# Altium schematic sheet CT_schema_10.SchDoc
size 278 x 170 mm
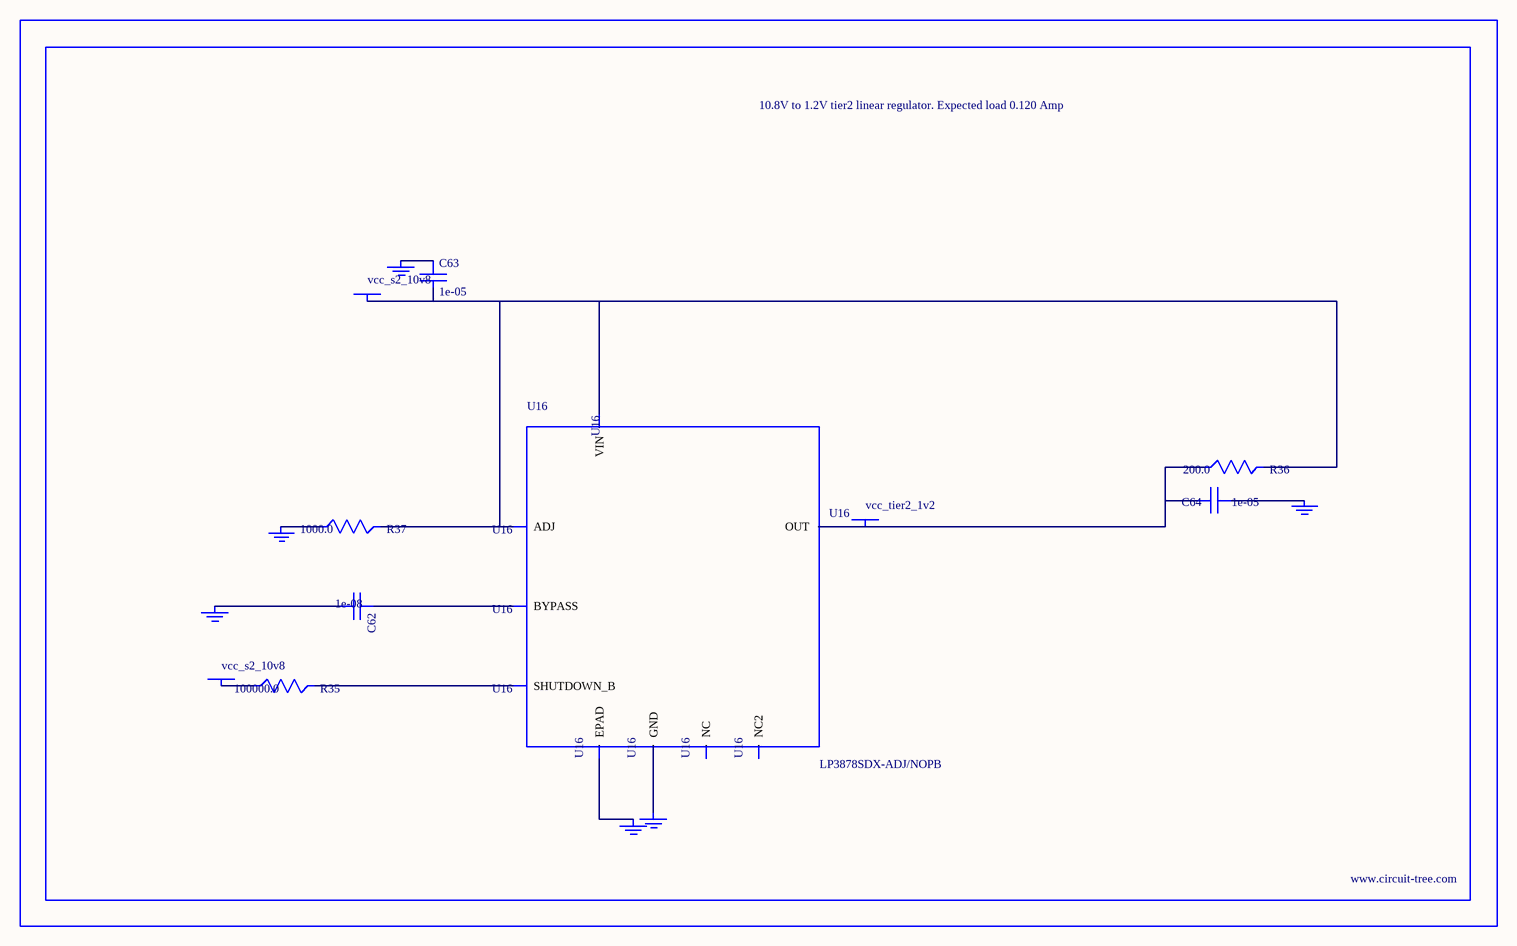
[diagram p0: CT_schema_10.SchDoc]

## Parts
BORDER9  (no value)
C62  1e-08  [C0402]
C63  1e-05  [C1206]
C64  1e-05  [C0805]
GND_INSTANCE_9_0  (no value)
GND_INSTANCE_9_1  (no value)
GND_INSTANCE_9_2  (no value)
GND_INSTANCE_9_3  (no value)
GND_INSTANCE_9_4  (no value)
GND_INSTANCE_9_5  (no value)
POWER_INSTANCE_9_0  vcc_s2_10v8
POWER_INSTANCE_9_1  vcc_s2_10v8
POWER_INSTANCE_9_2  vcc_tier2_1v2
R35  100000.0  [R0603]
R36  200.0  [R0603]
R37  1000.0  [R0603]
U16  LP3878SDX-ADJ/NOPB  [WSON-8]

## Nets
NetC62_1: C62.1 U16.1(BYPASS)
NetC62_2: C62.2 GND_INSTANCE_9_0.0(GND)
NetC63_1: C63.1 GND_INSTANCE_9_1.0(GND)
NetC63_2: C63.2 POWER_INSTANCE_9_0.0(PWR) R36.2 R37.2 U16.4(VIN) U16.6(ADJ)
NetC64_1: C64.1 GND_INSTANCE_9_2.0(GND)
NetC64_2: C64.2 POWER_INSTANCE_9_2.0(PWR) R36.1 U16.5(OUT)
NetGND_INSTANCE_9_3_0: GND_INSTANCE_9_3.0(GND) R37.1
NetGND_INSTANCE_9_4_0: GND_INSTANCE_9_4.0(GND) U16.PAD(EPAD)
NetGND_INSTANCE_9_5_0: GND_INSTANCE_9_5.0(GND) U16.3(GND)
NetPOWER_INSTANCE_9_1_0: POWER_INSTANCE_9_1.0(PWR) R35.1
NetR35_2: R35.2 U16.8(SHUTDOWN_B)

Not connected (* = marked no-connect by the designer): U16 2(NC) 7(NC2)

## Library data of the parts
BORDER9 = BORDER_PAGE9
C62 = C0402C103K3RAC
C63 = C1206C106K3RACTU
C64 = GRM219R60J106ME19D
GND_INSTANCE_9_0-GND_INSTANCE_9_5 = GND
POWER_INSTANCE_9_0-POWER_INSTANCE_9_2 = PWR
R35 = RC0603JR-07100KL
R36 = RC0603JR-07200RL
R37 = RC0603JR-071KL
